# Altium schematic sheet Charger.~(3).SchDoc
size A3; SheetNumber: 2; SheetTotal: 2
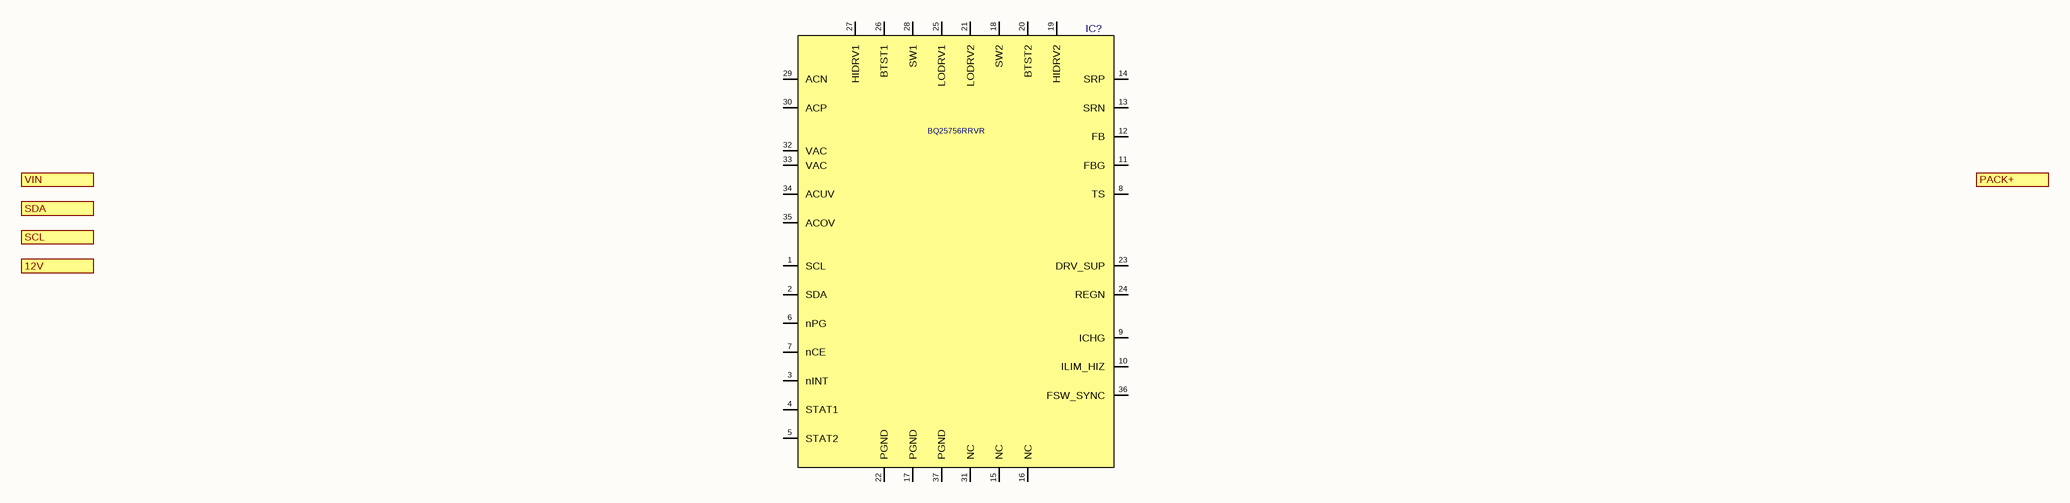
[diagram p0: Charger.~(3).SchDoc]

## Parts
IC?  BQ25756RRVR  [VQFN-36(5x6)]

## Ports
12V (see Arhitecture[5B]), PACK+ (see Arhitecture[6B]), SCL (see Arhitecture[5B]), SDA (see Arhitecture[5B]), VIN (see Arhitecture[5B])

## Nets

Not connected (* = marked no-connect by the designer): IC? 1(SCL) 2(SDA) 3(nINT) 4(STAT1) 5(STAT2) 6(nPG) 7(nCE) 8(TS) 9(ICHG) 10(ILIM_HIZ) 11(FBG) 12(FB) 13(SRN) 14(SRP) 15(NC) 16(NC) 17(PGND) 18(SW2) 19(HIDRV2) 20(BTST2) 21(LODRV2) 22(PGND) 23(DRV_SUP) 24(REGN) 25(LODRV1) 26(BTST1) 27(HIDRV1) 28(SW1) 29(ACN) 30(ACP) 31(NC) 32(VAC) 33(VAC) 34(ACUV) 35(ACOV) 36(FSW_SYNC) 37(PGND)

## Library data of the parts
IC? = BQ25756RRVR: Charger IC; Manufacturer: Texas Instruments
